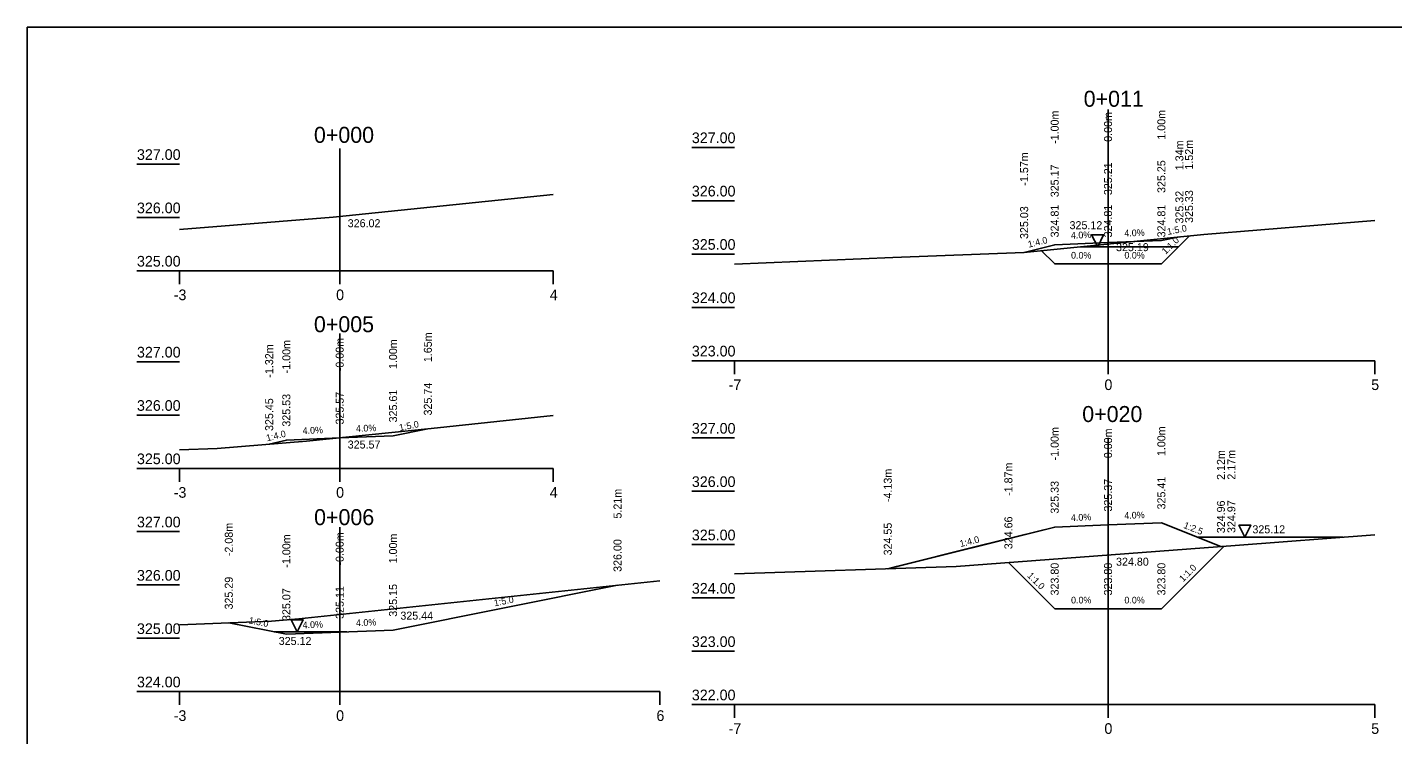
# Model space of a CAD drawing. Extents: x -560313 to -560271, y -1162459.6 to -1162429.9.
# Drawn here: x -560313.01 to -560287.42, y -1162443.18 to -1162429.91 of the extents above; entities that cross this region are included whole.
import ezdxf

# ---------------------------------------------------------------- set-up
doc = ezdxf.new("R2010")
doc.units = 0
for name, color, linetype in [('16', 7, 'Continuous'), ('21', 7, 'Continuous'), ('28', 7, 'Continuous'), ('59', 7, 'Continuous'), ('Body pricny rez', 7, 'Continuous'), ('Popis pricneho profilu', 7, 'Continuous')]:
    doc.layers.add(name, color=color, linetype=linetype)

msp = doc.modelspace()

# ---------------------------------------------------------------- linework, layer by layer
for p, q in [((-560271.013, -1162429.91), (-560313.013, -1162429.91)), ((-560313.013, -1162429.91), (-560313.013, -1162459.61))]:
    msp.add_line(p, q)
for points in [[(-560310.158, -1162433.703), (-560307.279, -1162433.471), (-560303.158, -1162433.046)], [(-560299.758, -1162434.351), (-560296.794, -1162434.224), (-560294.338, -1162434.131), (-560290.961, -1162433.794), (-560287.758, -1162433.532)], [(-560294.33, -1162434.13), (-560293.758, -1162433.987), (-560292.758, -1162433.947), (-560291.758, -1162433.907), (-560291.42, -1162433.84)], [(-560293.758, -1162433.987), (-560294.33, -1162434.13)], [(-560294.018, -1162434.087), (-560293.758, -1162434.347), (-560293.082, -1162434.347), (-560292.758, -1162434.347), (-560292.082, -1162434.347), (-560291.758, -1162434.347), (-560291.618, -1162434.207), (-560291.24, -1162433.829)], [(-560292.758, -1162433.947), (-560293.758, -1162433.987)], [(-560292.758, -1162433.947), (-560291.758, -1162433.907)], [(-560291.758, -1162434.347), (-560291.24, -1162433.829)], [(-560291.758, -1162433.907), (-560291.42, -1162433.84)], [(-560293.272, -1162434.024), (-560291.435, -1162434.024)], [(-560292.758, -1162434.347), (-560293.758, -1162434.347)], [(-560292.758, -1162434.347), (-560291.758, -1162434.347)], [(-560310.158, -1162437.836), (-560309.452, -1162437.808), (-560307.778, -1162437.673), (-560305.444, -1162437.432), (-560303.158, -1162437.19)], [(-560308.48, -1162437.73), (-560308.158, -1162437.649), (-560307.158, -1162437.609), (-560306.158, -1162437.569), (-560305.506, -1162437.439)], [(-560307.158, -1162437.609), (-560306.158, -1162437.569)], [(-560306.158, -1162437.569), (-560305.506, -1162437.439)], [(-560308.158, -1162437.649), (-560308.48, -1162437.73)], [(-560307.158, -1162437.609), (-560308.158, -1162437.649)], [(-560296.886, -1162440.063), (-560296.72, -1162440.021), (-560295.202, -1162439.642), (-560293.758, -1162439.281), (-560292.758, -1162439.241), (-560291.758, -1162439.201), (-560290.642, -1162439.647)], [(-560293.758, -1162439.281), (-560296.886, -1162440.063)], [(-560292.758, -1162439.241), (-560293.758, -1162439.281)], [(-560292.758, -1162439.241), (-560291.758, -1162439.201)], [(-560291.758, -1162439.201), (-560290.642, -1162439.647)], [(-560299.758, -1162440.157), (-560295.602, -1162440.021), (-560290.378, -1162439.627), (-560287.758, -1162439.427)], [(-560294.625, -1162439.947), (-560293.758, -1162440.814), (-560292.758, -1162440.814), (-560291.758, -1162440.814), (-560290.587, -1162439.643)], [(-560291.758, -1162440.814), (-560290.587, -1162439.643)], [(-560291.079, -1162439.472), (-560288.348, -1162439.472)], [(-560293.758, -1162440.814), (-560294.625, -1162439.947)], [(-560310.158, -1162441.114), (-560308.437, -1162441.045), (-560307.924, -1162441.003), (-560307.21, -1162440.93), (-560301.158, -1162440.287)], [(-560306.158, -1162441.213), (-560301.951, -1162440.372)], [(-560292.758, -1162440.814), (-560293.758, -1162440.814)], [(-560292.758, -1162440.814), (-560291.758, -1162440.814)], [(-560308.158, -1162441.293), (-560309.237, -1162441.077)], [(-560308.385, -1162441.247), (-560307.023, -1162441.247)], [(-560307.158, -1162441.253), (-560308.158, -1162441.293)], [(-560307.158, -1162441.253), (-560306.158, -1162441.213)]]:
    msp.add_lwpolyline(points)
for points in [[(-560292.952, -1162434.024), (-560293.065, -1162433.799), (-560292.84, -1162433.799)], [(-560290.194, -1162439.472), (-560290.306, -1162439.247), (-560290.081, -1162439.247)], [(-560307.955, -1162441.247), (-560308.067, -1162441.022), (-560307.842, -1162441.022)]]:
    msp.add_lwpolyline(points, close=True)
at = {"layer": '16'}
for p, q in [((-560310.158, -1162434.477), (-560303.158, -1162434.477)), ((-560299.758, -1162436.162), (-560287.758, -1162436.162)), ((-560310.158, -1162438.182), (-560303.158, -1162438.182)), ((-560310.158, -1162442.367), (-560301.158, -1162442.367)), ((-560299.758, -1162442.61), (-560287.758, -1162442.61))]:
    msp.add_line(p, q, dxfattribs=at)
at = {"layer": '21'}
for p, q in [((-560300.558, -1162432.162), (-560299.758, -1162432.162)), ((-560310.958, -1162432.477), (-560310.158, -1162432.477)), ((-560300.558, -1162433.162), (-560299.758, -1162433.162)), ((-560310.958, -1162433.477), (-560310.158, -1162433.477)), ((-560300.558, -1162434.162), (-560299.758, -1162434.162)), ((-560310.958, -1162434.477), (-560310.158, -1162434.477)), ((-560300.558, -1162435.162), (-560299.758, -1162435.162)), ((-560310.958, -1162436.182), (-560310.158, -1162436.182)), ((-560300.558, -1162436.162), (-560299.758, -1162436.162)), ((-560310.958, -1162437.182), (-560310.158, -1162437.182)), ((-560300.558, -1162437.61), (-560299.758, -1162437.61)), ((-560310.958, -1162438.182), (-560310.158, -1162438.182)), ((-560300.558, -1162438.61), (-560299.758, -1162438.61)), ((-560310.958, -1162439.367), (-560310.158, -1162439.367)), ((-560300.558, -1162439.61), (-560299.758, -1162439.61)), ((-560310.958, -1162440.367), (-560310.158, -1162440.367)), ((-560300.558, -1162440.61), (-560299.758, -1162440.61)), ((-560310.958, -1162441.367), (-560310.158, -1162441.367)), ((-560300.558, -1162441.61), (-560299.758, -1162441.61)), ((-560310.958, -1162442.367), (-560310.158, -1162442.367)), ((-560300.558, -1162442.61), (-560299.758, -1162442.61))]:
    msp.add_line(p, q, dxfattribs=at)
at = {"layer": '28'}
for p, q in [((-560292.758, -1162431.453), (-560292.758, -1162436.162)), ((-560307.158, -1162432.185), (-560307.158, -1162434.477)), ((-560307.158, -1162435.649), (-560307.158, -1162438.182)), ((-560292.758, -1162437.61), (-560292.758, -1162442.61)), ((-560307.158, -1162439.285), (-560307.158, -1162442.367))]:
    msp.add_line(p, q, dxfattribs=at)
at = {"layer": '59'}
for p, q in [((-560310.158, -1162434.727), (-560310.158, -1162434.477)), ((-560307.158, -1162434.727), (-560307.158, -1162434.477)), ((-560303.158, -1162434.727), (-560303.158, -1162434.477)), ((-560299.758, -1162436.412), (-560299.758, -1162436.162)), ((-560292.758, -1162436.412), (-560292.758, -1162436.162)), ((-560287.758, -1162436.412), (-560287.758, -1162436.162)), ((-560310.158, -1162438.432), (-560310.158, -1162438.182)), ((-560307.158, -1162438.432), (-560307.158, -1162438.182)), ((-560303.158, -1162438.432), (-560303.158, -1162438.182)), ((-560310.158, -1162442.617), (-560310.158, -1162442.367)), ((-560307.158, -1162442.617), (-560307.158, -1162442.367)), ((-560301.158, -1162442.617), (-560301.158, -1162442.367)), ((-560299.758, -1162442.86), (-560299.758, -1162442.61)), ((-560292.758, -1162442.86), (-560292.758, -1162442.61)), ((-560287.758, -1162442.86), (-560287.758, -1162442.61))]:
    msp.add_line(p, q, dxfattribs=at)

# ---------------------------------------------------------------- texts
for s, height, p in [('0+011', 0.3, (-560293.214, -1162431.4)), ('0+000', 0.3, (-560307.641, -1162432.077)), ('325.12', 0.15, (-560293.479, -1162433.696)), ('0+005', 0.3, (-560307.641, -1162435.628)), ('0+020', 0.3, (-560293.241, -1162437.312)), ('0+006', 0.3, (-560307.638, -1162439.245)), ('325.12', 0.15, (-560290.052, -1162439.399)), ('325.12', 0.15, (-560308.301, -1162441.492))]:
    msp.add_text(s, height=height).set_placement(p)
for s, rotation, p in [('1:5.0', 11.3099, (-560291.638, -1162433.805)), ('1:4.0', 14.0362, (-560294.243, -1162434.044)), ('1:1.0', 45, (-560291.677, -1162434.178)), ('1:5.0', 11.3099, (-560306.031, -1162437.48)), ('1:4.0', 14.0362, (-560308.518, -1162437.675)), ('1:2.5', 338.1986, (-560291.354, -1162439.295)), ('1:4.0', 14.0362, (-560295.521, -1162439.657)), ('1:1.0', 315, (-560294.281, -1162440.202)), ('1:1.0', 45, (-560291.351, -1162440.318)), ('1:5.0', 11.3099, (-560304.253, -1162440.768)), ('1:5.0', 348.6901, (-560308.871, -1162441.086))]:
    msp.add_text(s, height=0.125, rotation=rotation).set_placement(p)
at = {"layer": '16'}
for p in [(-560293.451, -1162433.875), (-560292.451, -1162433.835), (-560307.851, -1162437.537), (-560306.851, -1162437.497), (-560293.451, -1162439.169), (-560292.451, -1162439.129), (-560307.851, -1162441.181), (-560306.851, -1162441.141)]:
    msp.add_text('4.0%', height=0.125, rotation=2.2906, dxfattribs=at).set_placement(p)
for p in [(-560293.451, -1162434.247), (-560292.451, -1162434.247), (-560293.451, -1162440.714), (-560292.451, -1162440.714)]:
    msp.add_text('0.0%', height=0.125, dxfattribs=at).set_placement(p)
at = {"layer": '21'}
for s, p in [('327.00', (-560300.558, -1162432.082)), ('327.00', (-560310.958, -1162432.397)), ('326.00', (-560300.558, -1162433.082)), ('326.00', (-560310.958, -1162433.397)), ('325.00', (-560300.558, -1162434.082)), ('325.00', (-560310.958, -1162434.397)), ('-3', (-560310.269, -1162435.027)), ('0', (-560307.225, -1162435.027)), ('4', (-560303.221, -1162435.027)), ('324.00', (-560300.558, -1162435.082)), ('327.00', (-560310.958, -1162436.102)), ('323.00', (-560300.558, -1162436.082)), ('-7', (-560299.869, -1162436.712)), ('0', (-560292.825, -1162436.712)), ('5', (-560287.825, -1162436.712)), ('326.00', (-560310.958, -1162437.102)), ('327.00', (-560300.558, -1162437.53)), ('325.00', (-560310.958, -1162438.102)), ('326.00', (-560300.558, -1162438.53)), ('-3', (-560310.269, -1162438.732)), ('0', (-560307.225, -1162438.732)), ('4', (-560303.221, -1162438.732)), ('327.00', (-560310.958, -1162439.287)), ('325.00', (-560300.558, -1162439.53)), ('326.00', (-560310.958, -1162440.287)), ('324.00', (-560300.558, -1162440.53)), ('325.00', (-560310.958, -1162441.287)), ('323.00', (-560300.558, -1162441.53)), ('324.00', (-560310.958, -1162442.287)), ('322.00', (-560300.558, -1162442.53)), ('-3', (-560310.269, -1162442.917)), ('0', (-560307.225, -1162442.917)), ('6', (-560301.221, -1162442.917)), ('-7', (-560299.869, -1162443.16)), ('0', (-560292.825, -1162443.16)), ('5', (-560287.825, -1162443.16))]:
    msp.add_text(s, height=0.2, dxfattribs=at).set_placement(p)
at = {"layer": '59'}
for s, p in [('326.02', (-560307.008, -1162433.659)), ('325.19', (-560292.608, -1162434.108)), ('325.57', (-560307.008, -1162437.809)), ('324.80', (-560292.608, -1162440.006)), ('325.44', (-560306.021, -1162441.018))]:
    msp.add_text(s, height=0.15, dxfattribs=at).set_placement(p)
at = {"layer": 'Body pricny rez'}
for p in [(-560293.758, -1162433.987), (-560292.758, -1162433.947), (-560291.758, -1162433.907), (-560291.421, -1162433.84), (-560291.24, -1162433.829), (-560294.33, -1162434.13), (-560293.758, -1162434.347), (-560292.758, -1162434.347), (-560291.758, -1162434.347), (-560306.158, -1162437.57), (-560305.507, -1162437.439), (-560308.48, -1162437.73), (-560308.158, -1162437.65), (-560307.158, -1162437.61), (-560293.758, -1162439.281), (-560292.758, -1162439.241), (-560291.758, -1162439.201), (-560290.587, -1162439.643), (-560290.643, -1162439.648), (-560296.886, -1162440.063), (-560294.625, -1162439.947), (-560301.952, -1162440.372), (-560293.758, -1162440.814), (-560292.758, -1162440.814), (-560291.758, -1162440.814), (-560309.237, -1162441.078), (-560308.158, -1162441.293), (-560307.158, -1162441.253), (-560306.158, -1162441.213)]:
    msp.add_text('+', height=0.001, dxfattribs=at).set_placement(p)
at = {"layer": 'Popis pricneho profilu'}
for s, p in [('-1.00m', (-560293.683, -1162432.097)), ('0.00m', (-560292.683, -1162432.057)), ('1.00m', (-560291.683, -1162432.017)), ('1.34m', (-560291.345, -1162432.59)), ('1.52m', (-560291.165, -1162432.579)), ('-1.57m', (-560294.255, -1162432.88)), ('325.21', (-560292.683, -1162433.057)), ('325.25', (-560291.683, -1162433.017)), ('325.17', (-560293.683, -1162433.097)), ('325.32', (-560291.345, -1162433.59)), ('325.33', (-560291.165, -1162433.579)), ('324.81', (-560293.683, -1162433.85)), ('324.81', (-560292.683, -1162433.85)), ('324.81', (-560291.683, -1162433.85)), ('325.03', (-560294.255, -1162433.88)), ('-1.00m', (-560308.083, -1162436.399)), ('-0.00m', (-560307.083, -1162436.359)), ('1.00m', (-560306.083, -1162436.319)), ('1.65m', (-560305.431, -1162436.189)), ('-1.32m', (-560308.405, -1162436.48)), ('325.53', (-560308.083, -1162437.399)), ('325.57', (-560307.083, -1162437.359)), ('325.61', (-560306.083, -1162437.319)), ('325.74', (-560305.431, -1162437.189)), ('325.45', (-560308.405, -1162437.48)), ('-1.00m', (-560293.683, -1162438.031)), ('0.00m', (-560292.683, -1162437.991)), ('1.00m', (-560291.683, -1162437.951)), ('2.12m', (-560290.567, -1162438.397)), ('2.17m', (-560290.371, -1162438.393)), ('-1.87m', (-560294.55, -1162438.697)), ('-4.13m', (-560296.811, -1162438.813)), ('325.41', (-560291.683, -1162438.951)), ('5.21m', (-560301.876, -1162439.122)), ('325.33', (-560293.683, -1162439.031)), ('325.37', (-560292.683, -1162438.991)), ('324.96', (-560290.567, -1162439.397)), ('324.97', (-560290.371, -1162439.393)), ('324.66', (-560294.55, -1162439.697)), ('-2.08m', (-560309.162, -1162439.827)), ('324.55', (-560296.811, -1162439.813)), ('-1.00m', (-560308.083, -1162440.043)), ('-0.00m', (-560307.083, -1162440.003)), ('1.00m', (-560306.083, -1162439.963)), ('326.00', (-560301.876, -1162440.122)), ('323.80', (-560293.683, -1162440.564)), ('323.80', (-560292.683, -1162440.564)), ('323.80', (-560291.683, -1162440.564)), ('325.29', (-560309.162, -1162440.827)), ('325.11', (-560307.083, -1162441.003)), ('325.15', (-560306.083, -1162440.963)), ('325.07', (-560308.083, -1162441.043))]:
    msp.add_text(s, height=0.15, rotation=90, dxfattribs=at).set_placement(p)

doc.saveas('drawing.dxf')
